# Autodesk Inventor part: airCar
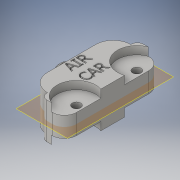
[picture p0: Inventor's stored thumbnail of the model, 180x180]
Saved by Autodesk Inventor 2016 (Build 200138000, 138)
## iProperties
Created: 2017-02
Part Number: airCar
Material: Generic
Document SubType Name: Modeling
Designer: Corey
Density: 1 g/cm^3
Appearance: Default
Author: Corey
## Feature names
1. Extrusion1
2. Extrusion2
3. Extrusion3
4. Extrusion4
5. Extrusion5
6. Extrusion6
7. Sweep1
8. Extrusion7
9. Extrusion8
10. Chamfer1
11. Mirror1
12. Extrusion9
13. Fillet3
14. Fillet4
15. Fillet5
16. Fillet6
## Parameters: n = 25.4 mm, d0 = 13.97 mm, d1 = 120 deg, d2 = 13.97 mm, d3 = 120 deg, d4 = 63.5 mm, d5 = 101.6 mm, d6 = 25.4 mm, d7 = 8.46667 mm, d8 = 0, d9 = 40.64 mm, d10 = 40.64 mm, d11 = 25.4 mm, d12 = 0, d13 = 21.16667 mm, d14 = 0, d15 = 8.89 mm, d16 = 8.89 mm, d17 = 23.70667 mm, d18 = 0, d19 = 27.94 mm, d20 = 27.94 mm, d21 = 8.46667 mm, d22 = 0, d23 = 1.48166 mm, d24 = 0, d25 = -19.05 mm, d27 = 7.62 mm, d28 = 7.62 mm, d29 = 0, d30 = 0, d31 = 7.62 mm, d32 = 7.62 mm, d33 = 12.7 mm, d34 = 12.7 mm, d35 = 0, d36 = 2.54 mm, d37 = 0, d38 = 1.5875 mm, d39 = 3.175 mm, d40 = 45 deg, d42 = 6.35 mm, d43 = 0, d44 = 40.64 mm, d45 = 63.5 mm, d46 = 52.3875 mm, d47 = 0, d49 = 40.64 mm, w = 40.64 mm, d50 = 19.05 mm, d51 = 12.7 mm, d52 = 6.35 mm, d53 = 6.35 mm, d54 = 12.7 mm, d55 = 12.7 mm
